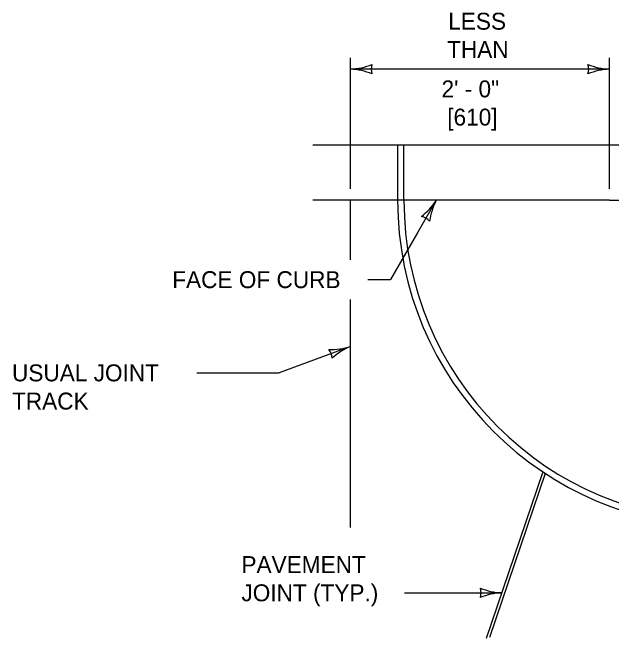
# Model space of a CAD drawing. Extents: x 49991.4 to 50021, y 49987.6 to 50011.4.
# Drawn here: x 50001.937 to 50004.062, y 49993.105 to 49995.325 of the extents above; entities that cross this region are included whole.
import ezdxf

# ---------------------------------------------------------------- set-up
doc = ezdxf.new("R2010")
doc.units = 0
for name, color, linetype in [('Level 1', 7, 'Continuous'), ('Level 2', 7, 'Continuous'), ('Level 3', 7, 'Continuous')]:
    doc.layers.add(name, color=color, linetype=linetype)

msp = doc.modelspace()

# ---------------------------------------------------------------- linework, layer by layer
at = {"layer": 'Level 1'}
for p, q in [((50005.9172, 49994.8543), (50003.0028, 49994.8543)), ((50004.055, 49994.6593), (50003.0028, 49994.6593)), ((50003.1361, 49994.4478), (50003.1361, 49994.6593)), ((50004.055, 49994.6593), (50004.865, 49994.6593)), ((50003.1361, 49993.4984), (50003.1361, 49994.3078)), ((50003.8175, 49993.6926), (50003.6181, 49993.1052)), ((50003.8273, 49993.6904), (50003.6297, 49993.1083))]:
    msp.add_line(p, q, dxfattribs=at)
msp.add_lwpolyline([(50003.326, 49994.6593), (50003.326, 49994.8543), (50003.3035, 49994.8543), (50003.3035, 49994.6593)], dxfattribs=at)
for radius in [1.1578, 1.1353]:
    msp.add_arc((50004.4612, 49994.6593), radius, 180, 0, dxfattribs=at)
at = {"layer": 'Level 2'}
for p in [(50003.1361, 49994.1408), (50002.5905, 49994.0472)]:
    msp.add_line(p, (50002.8825, 49994.0477), dxfattribs=at)
at = {"layer": 'Level 3'}
for p, q in [((50003.1361, 49994.6993), (50003.1361, 49995.1643)), ((50004.055, 49994.6993), (50004.055, 49995.1643)), ((50004.055, 49995.1243), (50003.1361, 49995.1243)), ((50003.4405, 49994.6593), (50003.3751, 49994.5461)), ((50003.3751, 49994.5461), (50003.278, 49994.3778)), ((50003.198, 49994.3778), (50003.278, 49994.3778)), ((50003.3282, 49993.2672), (50003.6731, 49993.2672))]:
    msp.add_line(p, q, dxfattribs=at)
for centre, radius, start, end in [((50003.1246, 49995.357), 0.233, 272.8273, 292.0772), ((50003.2643, 49995.1243), 0.0548, 162.1388, 197.8612), ((50004.0641, 49995.3464), 0.2223, 247.456, 267.6395), ((50003.9268, 49995.1243), 0.0548, 342.1388, 17.8612), ((50003.127, 49994.9021), 0.2223, 67.456, 87.6395), ((50004.0665, 49994.8916), 0.233, 92.8273, 112.0772), ((50003.2527, 49994.7783), 0.2223, 307.456, 327.6395), ((50003.6477, 49994.5529), 0.233, 152.8273, 172.0772), ((50003.3764, 49994.5482), 0.0548, 42.1388, 77.8612), ((50003.0682, 49994.3525), 0.2223, 267.6176, 287.8011), ((50003.0158, 49994.0966), 0.0548, 2.3004, 38.0228), ((50003.2271, 49993.9263), 0.233, 112.9889, 132.2388), ((50003.6822, 49993.4893), 0.2223, 247.456, 267.6395), ((50003.5449, 49993.2672), 0.0548, 342.1388, 17.8612), ((50003.6846, 49993.0345), 0.233, 92.8273, 112.0772)]:
    msp.add_arc(centre, radius, start, end, dxfattribs=at)

# ---------------------------------------------------------------- texts
at = {"layer": 'Level 2'}
for s, p in [('LESS', (50003.4831, 49995.2643)), ('THAN', (50003.479, 49995.1643)), ('2\' - 0"', (50003.4593, 49995.0243)), ('[610]', (50003.4796, 49994.9243)), ('FACE OF CURB', (50002.5035, 49994.3478)), ('USUAL JOINT ', (50001.9348, 49994.0172)), ('TRACK', (50001.9348, 49993.9172)), ('PAVEMENT', (50002.7491, 49993.3372)), ('JOINT (TYP.)', (50002.7491, 49993.2372))]:
    msp.add_text(s, height=0.06, dxfattribs=at).set_placement(p)

doc.saveas('drawing.dxf')
